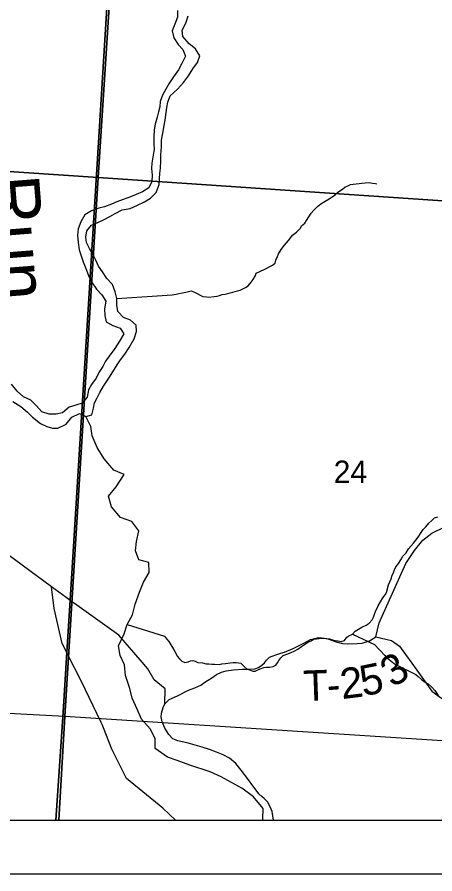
# Model space of a CAD drawing. Extents: x 0 to 34, y 0 to 22.
# Drawn here: x 5.391 to 6.168, y 14 to 15.594 of the extents above; entities that cross this region are included whole.
import ezdxf

# ---------------------------------------------------------------- set-up
doc = ezdxf.new("R2010")
doc.units = 0
for name, color, linetype in [('GM_X_Corporation', 7, 'Continuous'), ('GM_X_Major_River', 7, 'Continuous'), ('GM_X_Major_River_Text', 7, 'Continuous'), ('GM_X_Minor_River', 7, 'Continuous'), ('GM_X_Section_Text', 7, 'Continuous'), ('GM_X_Township_Road', 7, 'Continuous'), ('GM_X_Township_Road_Text', 7, 'Continuous'), ('SH_Data', 7, 'Continuous')]:
    doc.layers.add(name, color=color, linetype=linetype)

msp = doc.modelspace()

# ---------------------------------------------------------------- linework, layer by layer
at = {"layer": 'GM_X_Corporation'}
for points in [[(3.3441, 14.1), (8.9, 14.1), (8.9, 20.9), (2.1, 20.9), (2.1, 16.1353), (2.1457, 16.065), (2.3447, 15.6926), (2.4297, 15.5215), (2.465, 15.4504), (2.4884, 15.4033), (2.5769, 15.2135), (2.7849, 14.8403), (2.8931, 14.6544), (3.0297, 14.4867), (3.1386, 14.3654), (3.228, 14.2415)], [(4.6087, 16.3871), (5.6072, 16.3154), (5.5415, 15.2956), (4.5353, 15.3628)], [(5.4627, 14.1), (8.9, 14.1), (8.9, 16.2015), (7.873, 16.2628), (7.7162, 16.2721), (7.5782, 16.28), (6.6249, 16.3344), (6.6163, 16.2457), (5.9321, 16.289), (5.8351, 16.2952), (5.6497, 16.3069), (5.6022, 16.3258), (5.5809, 15.9822), (5.4893, 14.5091), (5.4833, 14.4122), (5.4763, 14.3006)], [(5.6072, 16.3154), (5.612, 16.3148), (6.621, 16.2504), (6.5568, 15.3381), (6.5491, 15.2271), (5.5415, 15.2956)], [(5.5415, 15.2956), (5.4795, 14.2928), (4.4813, 14.3453), (4.5353, 15.3628)], [(5.5415, 15.2956), (6.5491, 15.2271), (6.4864, 14.308), (6.4814, 14.2281), (5.4795, 14.2928)], [(4.4638, 14.1), (5.4686, 14.1), (5.4795, 14.2928), (4.4813, 14.3453)], [(5.4686, 14.1), (6.4745, 14.1), (6.4814, 14.2281), (5.4795, 14.2928)]]:
    msp.add_lwpolyline(points, close=True, dxfattribs=at)
msp.add_lwpolyline([(3.3441, 14.1), (5.4627, 14.1), (5.4763, 14.3006), (5.4833, 14.4122), (5.4893, 14.5091), (5.5809, 15.9822), (5.6022, 16.3258), (5.6497, 16.3069), (5.8351, 16.2952), (5.9321, 16.289), (6.6163, 16.2457), (6.6249, 16.3344), (6.6852, 17.2401), (6.6962, 17.3669), (6.7043, 17.4985), (6.7536, 18.2991)], dxfattribs=at)
at = {"layer": 'GM_X_Major_River'}
for points in [[(5.6895, 15.6062), (5.6891, 15.5933), (5.6845, 15.5808), (5.6792, 15.5679), (5.6826, 15.555), (5.6909, 15.5429), (5.6992, 15.5334), (5.7041, 15.5212), (5.698, 15.5084), (5.6911, 15.4959), (5.682, 15.4823), (5.6733, 15.4698), (5.6676, 15.4596), (5.6615, 15.4482), (5.6573, 15.4368), (5.6565, 15.427), (5.6542, 15.4175), (5.6512, 15.4077), (5.6477, 15.3944), (5.6462, 15.3842), (5.645, 15.3709), (5.645, 15.358), (5.6457, 15.3478)], [(5.6497, 15.2672), (5.6551, 15.2826), (5.6558, 15.2932), (5.6566, 15.3031), (5.6578, 15.3129), (5.6582, 15.3266), (5.6582, 15.3375), (5.6594, 15.3523), (5.6598, 15.3648), (5.6621, 15.3777), (5.6644, 15.3921), (5.6663, 15.4023), (5.6682, 15.416), (5.6694, 15.4258), (5.6713, 15.4353), (5.6759, 15.4474), (5.6896, 15.4599), (5.7006, 15.472), (5.7101, 15.4845), (5.7181, 15.4977), (5.7268, 15.5094), (5.731, 15.5219), (5.7231, 15.5345), (5.7113, 15.5443), (5.6992, 15.5576), (5.6981, 15.5694), (5.7046, 15.5826), (5.7092, 15.5959)], [(5.6457, 15.3478), (5.6414, 15.3218), (5.6411, 15.3124), (5.6422, 15.2999), (5.6414, 15.2881), (5.6361, 15.276), (5.6244, 15.2688), (5.6127, 15.2638), (5.6021, 15.2593), (5.5881, 15.2543), (5.5764, 15.2501), (5.5662, 15.246), (5.5533, 15.241), (5.5431, 15.238), (5.5295, 15.2331), (5.5167, 15.2259), (5.5095, 15.213), (5.5042, 15.1997), (5.5031, 15.1872), (5.5042, 15.1743), (5.5065, 15.1606), (5.5095, 15.1512), (5.5136, 15.1386), (5.5189, 15.1258), (5.5238, 15.1132), (5.5295, 15.1011), (5.5386, 15.0878), (5.5488, 15.0769), (5.556, 15.0651), (5.5537, 15.0511), (5.5541, 15.0389), (5.5567, 15.0268), (5.5688, 15.02), (5.5824, 15.0151), (5.5892, 15.0044), (5.5816, 14.9912), (5.5726, 14.9775), (5.5624, 14.9631), (5.5555, 14.9536), (5.5503, 14.9438), (5.5431, 14.9324), (5.5382, 14.9221), (5.5295, 14.9104), (5.5238, 14.9001), (5.5211, 14.8865), (5.5121, 14.8755), (5.5003, 14.8721), (5.4879, 14.8679), (5.4754, 14.8577), (5.4637, 14.8554), (5.4504, 14.8554), (5.4368, 14.8592), (5.4266, 14.8705), (5.4164, 14.8811), (5.4028, 14.8876), (5.3911, 14.8978), (5.3805, 14.9107)], [(5.3828, 14.8788), (5.3975, 14.8694), (5.4104, 14.8588), (5.4194, 14.8493), (5.4346, 14.8379), (5.4463, 14.8319), (5.4565, 14.8292), (5.4667, 14.8288), (5.4818, 14.8364), (5.4928, 14.8497), (5.5068, 14.8562), (5.5189, 14.8508), (5.5298, 14.8539), (5.5328, 14.8664), (5.5351, 14.8759), (5.54, 14.8854), (5.545, 14.8956), (5.5518, 14.9074), (5.5616, 14.9222), (5.5688, 14.9339), (5.5771, 14.9468), (5.5831, 14.9563), (5.5911, 14.9665), (5.5994, 14.9794), (5.6089, 14.9954), (5.613, 15.0086), (5.6123, 15.0208), (5.6021, 15.0299), (5.5888, 15.0348), (5.5782, 15.0458), (5.5764, 15.0579), (5.5764, 15.07), (5.5733, 15.0829), (5.5681, 15.0962), (5.5575, 15.1076), (5.5495, 15.1201), (5.542, 15.1303), (5.5374, 15.1413), (5.5314, 15.1538), (5.5254, 15.1633), (5.5201, 15.1747), (5.5189, 15.1841), (5.5205, 15.1963), (5.5291, 15.2065), (5.5409, 15.2118), (5.553, 15.2172), (5.5635, 15.2225), (5.5734, 15.2282), (5.5866, 15.235), (5.601, 15.2376), (5.615, 15.2437), (5.6278, 15.2498), (5.6388, 15.2566), (5.6497, 15.2672)]]:
    msp.add_lwpolyline(points, dxfattribs=at)
at = {"layer": 'GM_X_Minor_River'}
for points in [[(5.5764, 15.07), (5.6795, 15.0771), (5.6871, 15.0785), (5.6921, 15.0795), (5.6989, 15.0809), (5.7046, 15.0823), (5.7099, 15.0834), (5.7145, 15.0845), (5.7209, 15.0821), (5.7258, 15.0793), (5.7318, 15.0766), (5.7366, 15.0742), (5.7431, 15.0733), (5.7472, 15.0729), (5.7579, 15.0738), (5.7632, 15.0749), (5.7674, 15.076), (5.7727, 15.0778), (5.778, 15.0784), (5.7833, 15.0795), (5.7875, 15.0809), (5.7925, 15.082), (5.797, 15.0831), (5.8012, 15.0845), (5.8058, 15.0856), (5.8111, 15.0881), (5.8161, 15.0907), (5.8211, 15.0937), (5.8265, 15.1004), (5.8304, 15.1057), (5.8343, 15.1132), (5.8359, 15.1177), (5.8504, 15.1243), (5.8665, 15.132), (5.8711, 15.1361), (5.8727, 15.1414), (5.8755, 15.1486), (5.8774, 15.1531), (5.8821, 15.1617), (5.8883, 15.1692), (5.8957, 15.1782), (5.9003, 15.1838), (5.9034, 15.1883), (5.9107, 15.1939), (5.9184, 15.2014), (5.92, 15.2055), (5.9265, 15.2107), (5.9297, 15.2156), (5.9339, 15.222), (5.9379, 15.2291), (5.9433, 15.2347), (5.9502, 15.2415), (5.956, 15.2463), (5.964, 15.2515), (5.9716, 15.2555), (5.9774, 15.2596), (5.9835, 15.2637), (5.9878, 15.2682), (5.9966, 15.2737), (6.0008, 15.2771), (6.0065, 15.2796), (6.0115, 15.2822), (6.0165, 15.2832), (6.0218, 15.2835), (6.0275, 15.2842), (6.0324, 15.2849), (6.0385, 15.2855), (6.046, 15.2858), (6.0525, 15.2849), (6.0578, 15.2841), (6.0602, 15.2835)], [(5.6478, 14.233), (5.6475, 14.2521), (5.6385, 14.2696), (5.6226, 14.2875), (5.614, 14.3065), (5.6049, 14.3266), (5.6008, 14.3445), (5.5925, 14.3688), (5.5907, 14.3886), (5.5824, 14.4065), (5.5794, 14.424), (5.5901, 14.4468), (5.5954, 14.4639), (5.6053, 14.4821), (5.6103, 14.5019), (5.6186, 14.5239), (5.6262, 14.5426), (5.6365, 14.5604), (5.6358, 14.579), (5.6173, 14.584), (5.6112, 14.6011), (5.6128, 14.6182), (5.6174, 14.6384), (5.6046, 14.6555), (5.5834, 14.6631), (5.5668, 14.6829), (5.5611, 14.7023), (5.5752, 14.7201), (5.59, 14.7426), (5.5707, 14.7509), (5.553, 14.7723), (5.5398, 14.7932), (5.5307, 14.8149), (5.5281, 14.8323), (5.5189, 14.8508)], [(5.5954, 14.4639), (5.6653, 14.442), (5.669, 14.4374), (5.6731, 14.432), (5.6771, 14.4263), (5.6801, 14.4209), (5.6841, 14.4136), (5.6867, 14.4094), (5.6889, 14.4048), (5.6933, 14.3998), (5.6974, 14.3959), (5.7031, 14.3932), (5.7091, 14.3942), (5.7137, 14.3964), (5.7179, 14.3971), (5.7224, 14.3955), (5.7273, 14.3931), (5.7356, 14.3926), (5.7428, 14.391), (5.7477, 14.3905), (5.753, 14.39), (5.7583, 14.3899), (5.7674, 14.3894), (5.772, 14.3905), (5.7784, 14.3915), (5.7871, 14.3925), (5.7928, 14.3932), (5.7985, 14.3931), (5.8072, 14.3918), (5.8135, 14.386), (5.8191, 14.3809), (5.8233, 14.3797), (5.8293, 14.3773), (5.8338, 14.3773), (5.8392, 14.3795), (5.8434, 14.3817), (5.8499, 14.3838), (5.8552, 14.3845), (5.8609, 14.3844), (5.8673, 14.3858), (5.8727, 14.3884), (5.8758, 14.3925), (5.8781, 14.3966), (5.882, 14.4019), (5.8859, 14.4064), (5.8931, 14.4085), (5.9007, 14.4115), (5.9065, 14.4144), (5.9133, 14.4181), (5.9202, 14.4229), (5.9333, 14.4314), (5.9379, 14.4336), (5.9428, 14.4366), (5.9478, 14.4369), (5.9584, 14.4386), (5.9626, 14.4385), (5.9675, 14.4377), (5.972, 14.4372), (5.978, 14.4356), (5.9829, 14.4344), (5.9882, 14.4335), (5.9943, 14.4323), (6, 14.4341), (6.0043, 14.4401), (6.0085, 14.443), (6.0153, 14.446), (6.02, 14.4516), (6.0326, 14.459), (6.0403, 14.4626), (6.0464, 14.4663), (6.0518, 14.4727), (6.0541, 14.4772), (6.0561, 14.4829), (6.0578, 14.4881), (6.0629, 14.4983), (6.0718, 14.5133), (6.0761, 14.5193), (6.0784, 14.5235), (6.0821, 14.5375), (6.0868, 14.5488), (6.0892, 14.5556), (6.0912, 14.5601), (6.0924, 14.5646), (6.0956, 14.571), (6.0994, 14.5755), (6.1064, 14.586), (6.108, 14.5906), (6.115, 14.5969), (6.1193, 14.6044), (6.1285, 14.6149), (6.1371, 14.6265), (6.1429, 14.6348), (6.1468, 14.6408), (6.1518, 14.6456), (6.1572, 14.6524), (6.163, 14.6576), (6.1676, 14.6621), (6.1737, 14.6643)], [(6.0153, 14.446), (6.0563, 14.4267), (6.0645, 14.4174), (6.0686, 14.4135), (6.0741, 14.4077), (6.0782, 14.4027), (6.0827, 14.3996), (6.0872, 14.3954), (6.095, 14.3895), (6.1044, 14.3852), (6.1112, 14.3817), (6.1157, 14.3797), (6.1209, 14.3773), (6.133, 14.371), (6.1371, 14.3672), (6.1438, 14.3617), (6.1505, 14.3567), (6.1558, 14.3536), (6.1628, 14.3474), (6.1684, 14.3408), (6.1743, 14.3316)], [(5.8481, 14.1), (5.8483, 14.1022), (5.8491, 14.1219), (5.831, 14.1432), (5.8091, 14.1592), (5.7887, 14.1706), (5.7706, 14.1805), (5.7502, 14.1897), (5.7123, 14.2019), (5.6889, 14.2111), (5.6708, 14.2172), (5.6478, 14.233)]]:
    msp.add_lwpolyline(points, dxfattribs=at)
at = {"layer": 'GM_X_Township_Road'}
for points in [[(5.4903, 14.508), (5.4895, 14.5086), (5.4821, 14.5139), (5.4548, 14.534), (5.36, 14.604), (5.3119, 14.6481), (5.2467, 14.6996)], [(5.6656, 14.3162), (5.6738, 14.3241), (5.6891, 14.3313), (5.7099, 14.3419), (5.7215, 14.3459), (5.7329, 14.3508), (5.7403, 14.3563), (5.7535, 14.3647), (5.7621, 14.3711), (5.7715, 14.3751), (5.7802, 14.3778), (5.7933, 14.3793), (5.8101, 14.3808), (5.8243, 14.381), (5.8332, 14.3813), (5.8401, 14.384), (5.8465, 14.388), (5.8515, 14.3927), (5.8552, 14.3976), (5.8606, 14.4028), (5.8723, 14.4073), (5.8814, 14.4107), (5.8886, 14.4127), (5.9045, 14.4194), (5.9256, 14.4297), (5.937, 14.4357), (5.9444, 14.4379), (5.9521, 14.4394), (5.9577, 14.4392), (5.969, 14.4372), (5.9847, 14.4318), (5.9968, 14.4284), (6.0065, 14.4277), (6.0239, 14.4284), (6.0333, 14.4293), (6.0468, 14.4335), (6.0588, 14.4412), (6.065, 14.4671), (6.1147, 14.5774), (6.1303, 14.6013), (6.1458, 14.6207), (6.1629, 14.6336), (6.1873, 14.6457)], [(5.4861, 14.4065), (5.4835, 14.4117), (5.4749, 14.4288), (5.46, 14.4936), (5.4548, 14.534)], [(5.6198, 14.3984), (5.5803, 14.4438), (5.5017, 14.4999), (5.4903, 14.508)], [(6.0588, 14.4412), (6.0875, 14.4342), (6.1024, 14.4238), (6.1139, 14.4079), (6.1253, 14.3921), (6.1629, 14.3396), (6.1808, 14.3267), (6.1858, 14.3208), (6.2225, 14.3089), (6.2349, 14.3064), (6.2439, 14.3068), (6.2637, 14.3083), (6.3, 14.3063), (6.3122, 14.3085), (6.3407, 14.3187)], [(5.5518, 14.2714), (5.5497, 14.2768), (5.5473, 14.2818), (5.5098, 14.359), (5.4861, 14.4065)], [(5.6596, 14.2981), (5.6597, 14.299), (5.6624, 14.3095), (5.6656, 14.3162), (5.6663, 14.3442), (5.6458, 14.3612), (5.6343, 14.3817), (5.6198, 14.3984)], [(5.8504, 14.14), (5.847, 14.1433), (5.841, 14.149), (5.8106, 14.1899), (5.7978, 14.2053), (5.7861, 14.215), (5.7745, 14.2217), (5.7621, 14.2266), (5.7492, 14.2316), (5.7351, 14.2358), (5.7094, 14.2429), (5.6901, 14.2474), (5.6807, 14.2514), (5.673, 14.2593), (5.6658, 14.2709), (5.6609, 14.2825), (5.6589, 14.2922), (5.6596, 14.2981)], [(5.6859, 14.1), (5.6618, 14.1224), (5.5945, 14.1772), (5.5671, 14.232), (5.5518, 14.2714)], [(5.8679, 14.1), (5.8653, 14.116), (5.8621, 14.1248), (5.8566, 14.1339), (5.8504, 14.14)]]:
    msp.add_lwpolyline(points, dxfattribs=at)
at = {"layer": 'SH_Data'}
for p, q in [((2.1, 14.1), (8.9, 14.1)), ((2, 14), (9, 14))]:
    msp.add_line(p, q, dxfattribs=at)

# ---------------------------------------------------------------- texts
at = {"layer": 'GM_X_Major_River_Text'}
msp.add_text('Run', height=0.09467, rotation=274.4922, dxfattribs=at).set_placement((5.3367, 15.2958))
at = {"layer": 'GM_X_Section_Text'}
msp.add_text('24', height=0.04186, rotation=0, dxfattribs=at).set_placement((5.9801, 14.7269))
at = {"layer": 'GM_X_Township_Road_Text'}
for s, rotation, p in [('3', 32.0494, (6.0899, 14.3452)), ('5', 11.452, (6.035, 14.33)), ('T', 2.0736, (5.9245, 14.3213)), ('2', 7.0637, (5.9956, 14.3249)), ('-', 4.1819, (5.9692, 14.3229))]:
    msp.add_text(s, height=0.0568, rotation=rotation, dxfattribs=at).set_placement(p)

doc.saveas('drawing.dxf')
